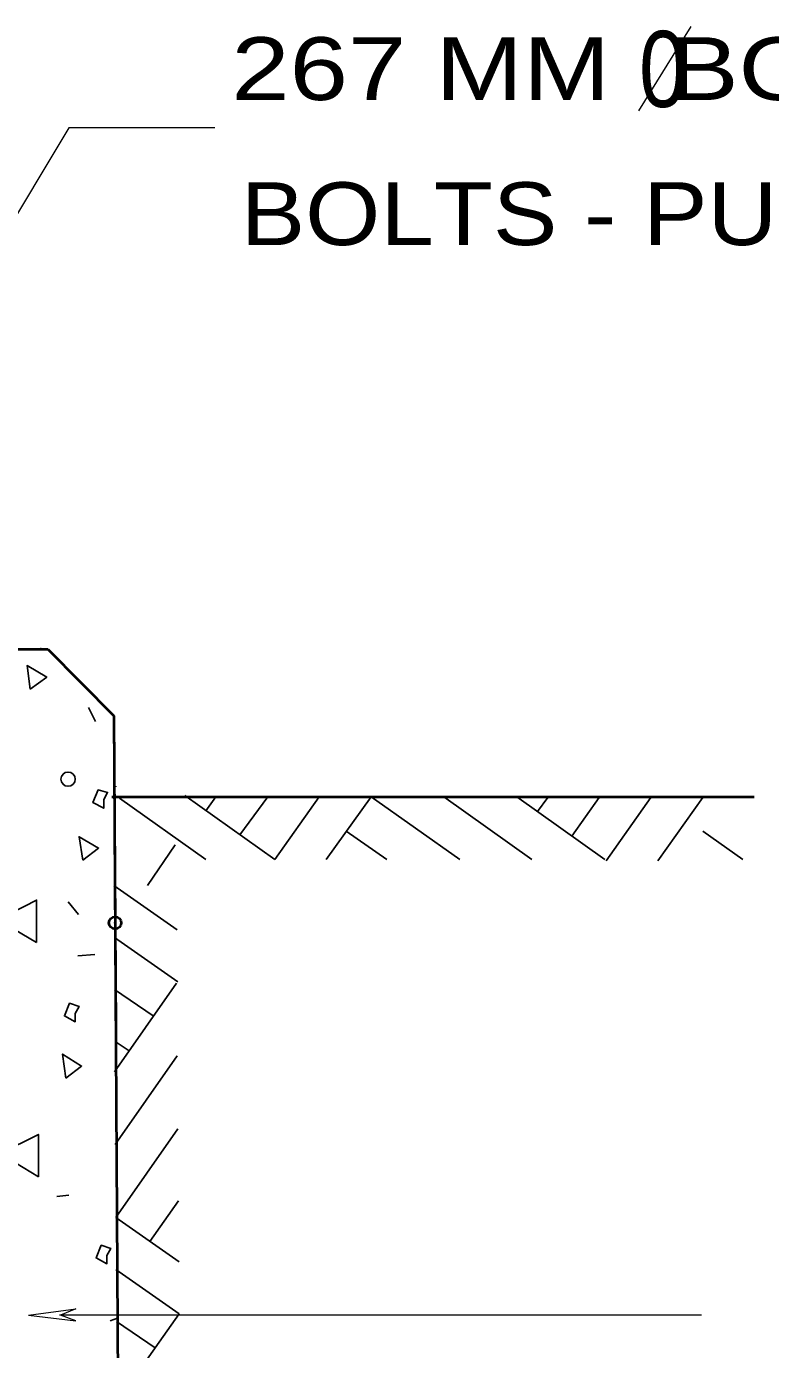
# Model space of a CAD drawing. Extents: x 312583 to 312854, y 144419 to 144597.
# Drawn here: x 312820.44 to 312829.45, y 144500.28 to 144516.29 of the extents above; entities that cross this region are included whole.
import ezdxf
from ezdxf.enums import TextEntityAlignment as Align

# ---------------------------------------------------------------- set-up
doc = ezdxf.new("R2010")
doc.units = 0
doc.header["$LTSCALE"] = 0.3
doc.header["$PDMODE"] = 32
doc.header["$PDSIZE"] = 0.15
doc.layers.add('1', color=7, linetype='Continuous', lineweight=40)
doc.layers.add('2', color=7, linetype='Continuous', lineweight=13)

msp = doc.modelspace()

# ---------------------------------------------------------------- linework, layer by layer
at = {"layer": '1'}
for p, q in [((312815.7682, 144508.7506), (312820.7055, 144508.7506)), ((312815.7682, 144508.7506), (312820.7055, 144508.7506)), ((312815.7682, 144508.7506), (312820.7055, 144508.7506)), ((312815.7682, 144508.7506), (312820.7055, 144508.7506)), ((312815.7682, 144508.7506), (312820.7055, 144508.7506)), ((312815.7682, 144508.7506), (312820.7055, 144508.7506)), ((312815.7682, 144508.7506), (312820.7055, 144508.7506)), ((312815.7682, 144508.7506), (312820.7055, 144508.7506)), ((312820.6212, 144508.7506), (312820.6135, 144508.7506)), ((312820.6212, 144508.7506), (312820.6135, 144508.7506)), ((312820.6212, 144508.7506), (312820.6135, 144508.7506)), ((312820.6212, 144508.7506), (312820.6135, 144508.7506)), ((312820.6212, 144508.7506), (312820.6135, 144508.7506)), ((312820.6212, 144508.7506), (312820.6135, 144508.7506)), ((312820.6212, 144508.7506), (312820.6135, 144508.7506)), ((312820.6212, 144508.7506), (312820.6135, 144508.7506)), ((312820.6288, 144508.7506), (312820.6288, 144508.7429)), ((312820.6288, 144508.7506), (312820.6288, 144508.7429)), ((312820.6288, 144508.7506), (312820.6288, 144508.7429)), ((312820.6288, 144508.7506), (312820.6288, 144508.7429)), ((312820.6288, 144508.7506), (312820.6288, 144508.7429)), ((312820.6288, 144508.7506), (312820.6288, 144508.7429)), ((312820.6288, 144508.7506), (312820.6288, 144508.7429)), ((312820.6288, 144508.7506), (312820.6288, 144508.7429)), ((312820.6288, 144508.7506), (312820.6288, 144508.7429)), ((312820.6288, 144508.7506), (312820.6288, 144508.7429)), ((312820.6288, 144508.7506), (312820.6288, 144508.7429)), ((312820.6288, 144508.7506), (312820.6288, 144508.7429)), ((312820.6288, 144508.7506), (312820.6288, 144508.7429)), ((312820.6288, 144508.7506), (312820.6288, 144508.7429)), ((312820.6288, 144508.7506), (312820.6288, 144508.7429)), ((312820.6288, 144508.7506), (312820.6288, 144508.7429)), ((312820.7055, 144508.7506), (312821.5028, 144507.9456)), ((312820.7055, 144508.7506), (312821.5028, 144507.9456)), ((312820.7055, 144508.7506), (312821.5028, 144507.9456)), ((312820.7055, 144508.7506), (312821.5028, 144507.9456)), ((312820.7055, 144508.7506), (312821.5028, 144507.9456)), ((312820.7055, 144508.7506), (312821.5028, 144507.9456)), ((312820.7055, 144508.7506), (312821.5028, 144507.9456)), ((312820.7055, 144508.7506), (312821.5028, 144507.9456)), ((312821.5028, 144507.9456), (312821.6178, 144489.4383)), ((312821.5028, 144507.9456), (312821.5258, 144504.1583)), ((312821.5028, 144507.9456), (312821.5258, 144504.1583)), ((312821.5028, 144507.9456), (312821.5258, 144504.1583)), ((312821.5028, 144507.9456), (312821.5258, 144504.1583)), ((312821.5028, 144507.9456), (312821.5258, 144504.1583)), ((312821.5028, 144507.9456), (312821.5258, 144504.1583)), ((312821.5028, 144507.9456), (312821.5258, 144504.1583)), ((312821.5182, 144507.0946), (312821.5182, 144507.0869)), ((312821.5182, 144507.0946), (312821.5182, 144507.0869)), ((312821.5182, 144507.0946), (312821.5182, 144507.0869)), ((312821.5182, 144507.0946), (312821.5182, 144507.0869)), ((312821.5182, 144507.0946), (312821.5182, 144507.0869)), ((312821.5182, 144507.0946), (312821.5182, 144507.0869)), ((312821.5182, 144507.0946), (312821.5182, 144507.0869)), ((312821.5182, 144507.0946), (312821.5182, 144507.0869)), ((312821.4798, 144506.9643), (312829.2538, 144506.9643)), ((312821.4798, 144506.9643), (312829.2538, 144506.9643)), ((312821.4798, 144506.9643), (312829.2538, 144506.9643)), ((312821.4798, 144506.9643), (312829.2538, 144506.9643)), ((312821.4798, 144506.9643), (312829.2538, 144506.9643)), ((312821.4798, 144506.9643), (312829.2538, 144506.9643)), ((312821.4798, 144506.9643), (312829.2538, 144506.9643)), ((312821.4798, 144506.9643), (312829.2538, 144506.9643))]:
    msp.add_line(p, q, dxfattribs=at)
at = {"layer": '1', "lineweight": 25}
for p, q in [((312821.1962, 144508.0453), (312821.2805, 144507.8766)), ((312823.4502, 144506.2053), (312822.3615, 144506.9796)), ((312822.6145, 144506.2053), (312821.5718, 144506.9489)), ((312822.7372, 144506.9643), (312822.6145, 144506.7956)), ((312823.3658, 144506.9643), (312823.0285, 144506.5043)), ((312823.9868, 144506.9643), (312823.4502, 144506.2053)), ((312824.6155, 144506.9643), (312824.0712, 144506.2053)), ((312825.6888, 144506.2053), (312824.6155, 144506.9643)), ((312826.5628, 144506.2053), (312825.4972, 144506.9643)), ((312827.4445, 144506.2053), (312826.3788, 144506.9643)), ((312826.7545, 144506.9566), (312826.6318, 144506.7879)), ((312827.3755, 144506.9566), (312827.0458, 144506.4889)), ((312828.0042, 144506.9566), (312827.4598, 144506.1899)), ((312828.6328, 144506.9566), (312828.0885, 144506.1899)), ((312824.8072, 144506.2053), (312824.3165, 144506.5503)), ((312829.1158, 144506.2053), (312828.6328, 144506.5503)), ((312822.2465, 144506.3816), (312821.9092, 144505.8909)), ((312821.5028, 144505.8909), (312822.2695, 144505.3543)), ((312821.5182, 144505.9523), (312821.5182, 144505.4386)), ((312820.9508, 144505.6916), (312821.0735, 144505.5383)), ((312821.5105, 144505.2623), (312822.2772, 144504.7256)), ((312821.0658, 144505.0399), (312821.2728, 144505.0553)), ((312822.2618, 144504.7103), (312821.5105, 144503.6369)), ((312821.5105, 144504.6336), (312821.9782, 144504.3116)), ((312821.5182, 144504.0049), (312821.6868, 144503.8899)), ((312822.2695, 144503.8286), (312821.5182, 144502.7553)), ((312822.2772, 144502.9469), (312821.5258, 144501.8736)), ((312820.8128, 144502.1266), (312820.9585, 144502.1419)), ((312822.2848, 144502.0729), (312821.9398, 144501.5823)), ((312821.5258, 144501.8736), (312822.2925, 144501.3369)), ((312821.5258, 144501.2449), (312822.2925, 144500.7083)), ((312821.4568, 144500.6239), (312821.5488, 144500.6546)), ((312822.2925, 144500.7083), (312821.5258, 144499.6196)), ((312821.5335, 144500.6163), (312822.0012, 144500.2943))]:
    msp.add_line(p, q, dxfattribs=at)
for points in [[(312820.4908, 144508.2676), (312820.6902, 144508.4133), (312820.4525, 144508.5513)], [(312821.3802, 144506.9336), (312821.4262, 144507.0179), (312821.3112, 144507.0486), (312821.2498, 144506.8953), (312821.3802, 144506.8263)], [(312821.1272, 144506.1976), (312821.3188, 144506.3433), (312821.0812, 144506.4813)], [(312820.5675, 144505.2009), (312820.5675, 144505.7146), (312820.0998, 144505.4769)], [(312821.0352, 144504.3423), (312821.0812, 144504.4266), (312820.9662, 144504.4649), (312820.9048, 144504.3116), (312821.0352, 144504.2426)], [(312820.9202, 144503.5603), (312821.1118, 144503.7059), (312820.8818, 144503.8516)], [(312820.5905, 144502.3643), (312820.5905, 144502.8779), (312820.1228, 144502.6479)], [(312821.4185, 144501.4136), (312821.4645, 144501.4979), (312821.3495, 144501.5363), (312821.2882, 144501.3829), (312821.4185, 144501.3139)]]:
    msp.add_lwpolyline(points, close=True, dxfattribs=at)
msp.add_circle((312820.9488, 144507.1777), 0.0865, dxfattribs=at)
at = {"layer": '1'}
msp.add_point((312821.5182, 144505.4386), dxfattribs=at)
at = {"layer": '2'}
for p, q in [((312828.4875, 144516.2869), (312827.8511, 144515.2673)), ((312820.9585, 144515.0603), (312817.7308, 144509.6859)), ((312822.726, 144515.0603), (312820.9585, 144515.0603)), ((312820.4678, 144500.6929), (312821.0428, 144500.7696)), ((312821.0428, 144500.7696), (312820.8588, 144500.6929)), ((312820.4678, 144500.6929), (312821.0428, 144500.6239)), ((312828.6175, 144500.6929), (312820.8435, 144500.6929)), ((312821.0428, 144500.6239), (312820.8588, 144500.6929))]:
    msp.add_line(p, q, dxfattribs=at)

# ---------------------------------------------------------------- texts
for s, width, p in [('267 MM  BOLT CIRCLE-20 MM', 1.25, (312822.9238, 144515.3966)), ('BOLTS - PUMP ROD COUPLINGS, ETC.', 1.15, (312823.0388, 144513.6409))]:
    msp.add_text(s, height=0.76, dxfattribs=dict(at, width=width)).set_placement(p)
at = {"layer": '2', "width": 0.85}
msp.add_text('0', height=0.92, rotation=180, dxfattribs=at).set_placement((312828.1501, 144516.2333), align=Align.CENTER)

doc.saveas('drawing.dxf')
